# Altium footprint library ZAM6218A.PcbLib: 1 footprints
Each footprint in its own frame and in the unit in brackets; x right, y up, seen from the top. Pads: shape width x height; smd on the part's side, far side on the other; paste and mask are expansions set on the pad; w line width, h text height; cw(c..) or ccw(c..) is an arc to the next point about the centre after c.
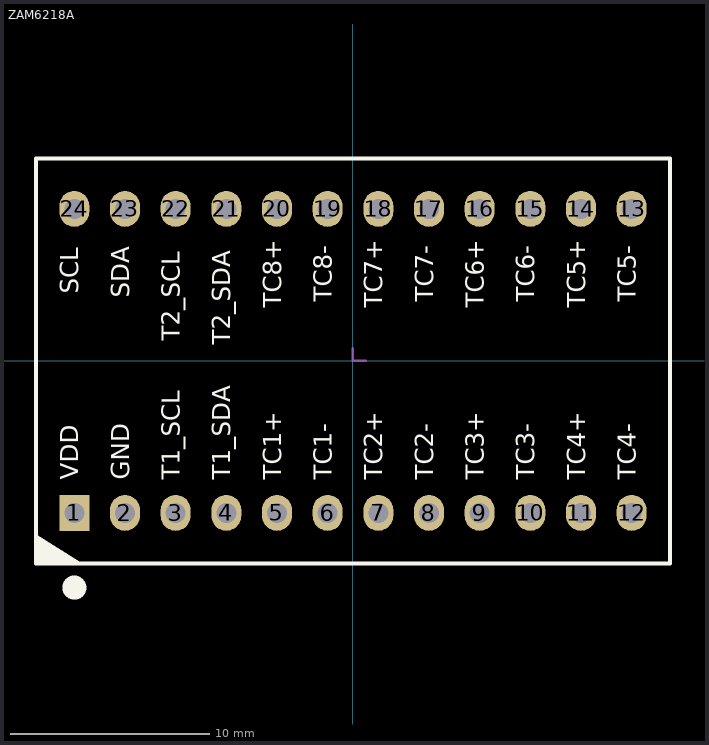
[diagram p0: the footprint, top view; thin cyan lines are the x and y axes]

## ZAM6218A [mm]
height 6.5
pads (24):
  rect 1.5x1.8 hole 1: 1(-13.97,-7.62)
  oval 1.5x1.8 hole 1: 2(-11.43,-7.62) 3(-8.89,-7.62) 4(-6.35,-7.62) 5(-3.81,-7.62) 6(-1.27,-7.62) 7(1.27,-7.62) 8(3.81,-7.62) 9(6.35,-7.62) 10(8.89,-7.62) 11(11.43,-7.62) 12(13.97,-7.62) 13(13.97,7.62) 14(11.43,7.62) 15(8.89,7.62) 16(6.35,7.62) 17(3.81,7.62) 18(1.27,7.62) 19(-1.27,7.62) 20(-3.81,7.62) 21(-6.35,7.62) 22(-8.89,7.62) 23(-11.43,7.62) 24(-13.97,7.62)
Top Overlay:
  circle w1: c-13.97,-11.368 r0.1
  region: -13.673,-10.15 -15.9,-10.15 -15.9,-8.69 -13.748,-10.038
  lines w0.2: -15.9,-10.15 15.9,-10.15 15.9,10.15 -15.9,10.15 -15.9,-10.15
  text "T2_SDA" at -5.842,0.796 h1.52
  text "TC8-" at -0.762,2.961 h1.52
  text "TC8+" at -3.302,2.657 h1.52
  text "TC7-" at 4.318,2.961 h1.52
  text "TC7+" at 1.778,2.657 h1.52
  text "TC6-" at 9.398,2.961 h1.52
  text "TC6+" at 6.858,2.657 h1.52
  text "TC4+" at 11.938,-5.969 h1.52
  text "TC4-" at 14.478,-5.969 h1.52
  text "TC3+" at 6.858,-5.969 h1.52
  text "TC3-" at 9.398,-5.969 h1.52
  text "TC2+" at 1.778,-5.969 h1.52
  text "TC2-" at 4.318,-5.969 h1.52
  text "T2_SCL" at -8.382,0.996 h1.52
  text "SDA" at -10.922,3.175 h1.52
  text "SCL" at -13.462,3.376 h1.52
  text "TC1-" at -0.762,-5.969 h1.52
  text "TC1+" at -3.302,-5.969 h1.52
  text "T1_SCL" at -8.382,-5.969 h1.52
  text "GND" at -10.922,-5.969 h1.52
  text "VDD" at -13.462,-5.969 h1.52
  text "TC5+" at 11.938,2.657 h1.52
  text "TC5-" at 14.478,2.961 h1.52
  text "T1_SDA" at -5.842,-5.969 h1.52
Mechanical 15:
  lines w0.127: 0,0.635 0,0 0.635,0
